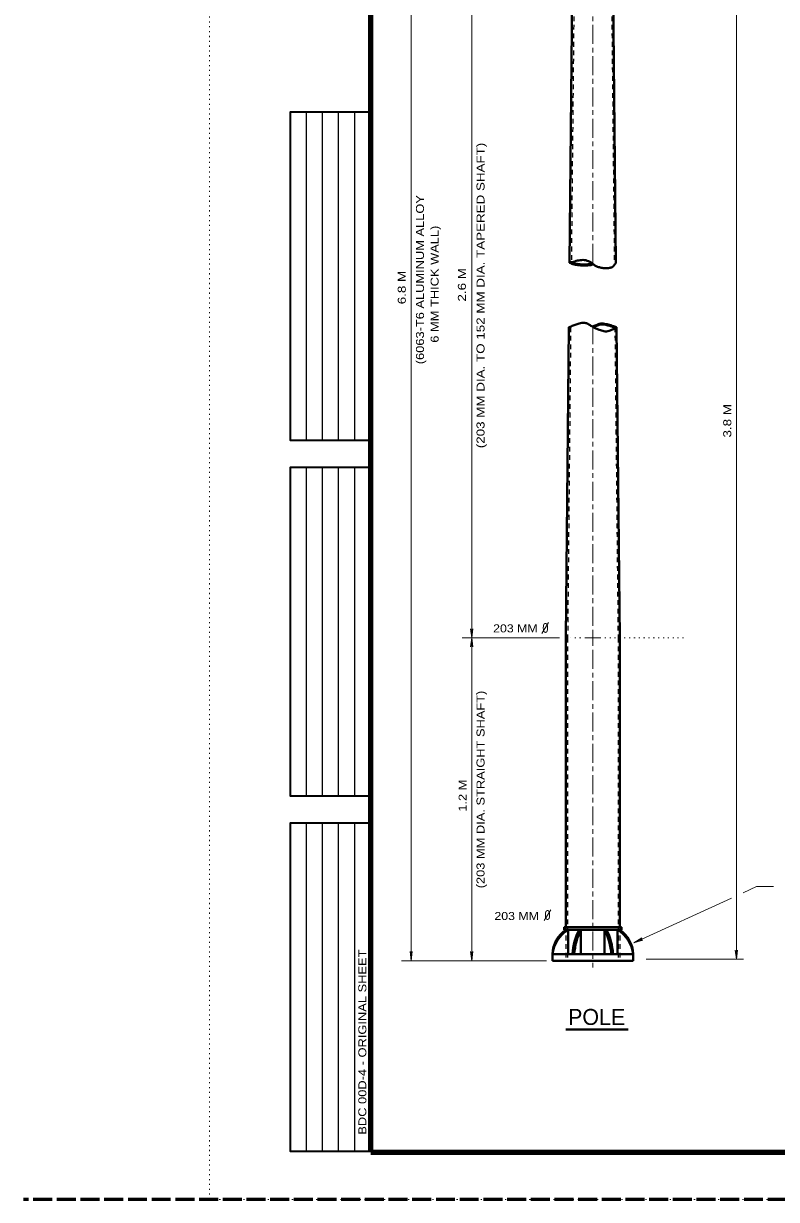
# Model space of a CAD drawing. Extents: x 312583 to 312854, y 144419 to 144597.
# Drawn here: x 312583.5 to 312655, y 144418.6 to 144530.3 of the extents above; entities that cross this region are included whole.
import ezdxf
from ezdxf.enums import TextEntityAlignment as Align

# ---------------------------------------------------------------- set-up
doc = ezdxf.new("R2010")
doc.units = 0
doc.header["$LTSCALE"] = 0.3
for name, pattern in [('DOTTED', [1.5, 0.3, -1.2]), ('LONG_DASH_SHORT_DASH', [9.9, 6, -1.2, 1.5, -1.2]), ('LONG_DASHED', [7.5, 6, -1.5]), ('SHORT_DASHED', [2.7, 1.5, -1.2])]:
    doc.linetypes.add(name, pattern=pattern)
for name, color, linetype, lineweight in [('1', 7, 'Continuous', 35), ('2', 7, 'Continuous', 13), ('62', 7, 'DOTTED', 13), ('63', 7, 'LONG_DASHED', 60)]:
    doc.layers.add(name, color=color, linetype=linetype, lineweight=lineweight)

msp = doc.modelspace()

# ---------------------------------------------------------------- linework, layer by layer
at = {"layer": '1', "lineweight": 40}
for p, q in [((312635.671, 144535.8063), (312635.3874, 144507.5393)), ((312639.5044, 144535.8063), (312639.788, 144507.5393)), ((312635.326, 144501.4136), (312635.0347, 144471.92)), ((312639.8494, 144501.4136), (312640.1484, 144471.92)), ((312635.0347, 144471.92), (312635.0347, 144444.4503)), ((312640.1484, 144471.92), (312640.1484, 144444.4503)), ((312634.8737, 144444.4503), (312637.5877, 144444.4503)), ((312634.8737, 144444.4503), (312634.8737, 144444.205)), ((312640.3017, 144444.4503), (312637.5877, 144444.4503)), ((312640.3017, 144444.4503), (312640.3017, 144444.205)), ((312634.8737, 144444.205), (312637.5877, 144444.205)), ((312635.2417, 144441.8896), (312635.2417, 144444.205)), ((312636.4684, 144444.205), (312636.4684, 144441.974)), ((312640.3017, 144444.205), (312637.5877, 144444.205)), ((312638.707, 144444.205), (312638.707, 144441.974)), ((312639.9414, 144441.8896), (312639.9414, 144444.205)), ((312633.7544, 144441.8896), (312637.5877, 144441.8896)), ((312633.7544, 144441.8896), (312633.7544, 144441.2533)), ((312633.7544, 144441.2533), (312637.5877, 144441.2533)), ((312641.421, 144441.8896), (312637.5877, 144441.8896)), ((312641.421, 144441.2533), (312637.5877, 144441.2533)), ((312641.421, 144441.8896), (312641.421, 144441.2533))]:
    msp.add_line(p, q, dxfattribs=at)
at = {"layer": '1', "linetype": 'SHORT_DASHED', "lineweight": 25}
for p, q in [((312635.832, 144535.8063), (312635.5484, 144507.5393)), ((312639.3434, 144535.8063), (312639.6347, 144507.3553)), ((312635.487, 144501.4136), (312635.1957, 144471.92)), ((312639.6884, 144501.4136), (312639.9874, 144471.92)), ((312635.1957, 144471.92), (312635.1957, 144444.4426)), ((312639.9874, 144471.92), (312639.9874, 144444.4426)), ((312635.0347, 144444.4503), (312635.0347, 144441.2533)), ((312635.1957, 144444.4503), (312635.1957, 144441.2533)), ((312639.9874, 144444.4503), (312639.9874, 144441.2533)), ((312640.1484, 144444.4503), (312640.1484, 144441.2533))]:
    msp.add_line(p, q, dxfattribs=at)
at = {"layer": '1', "linetype": 'LONG_DASH_SHORT_DASH', "lineweight": 13}
for p, q in [((312637.5877, 144507.5393), (312637.5877, 144534.6563)), ((312637.5877, 144473.07), (312637.5877, 144501.4136)), ((312637.5877, 144470.77), (312637.5877, 144440.6016))]:
    msp.add_line(p, q, dxfattribs=at)
at = {"layer": '1', "lineweight": 25}
for p, q in [((312610.4087, 144490.6573), (312610.4087, 144521.8756)), ((312611.9315, 144490.6573), (312611.9315, 144521.8756)), ((312613.4543, 144490.6573), (312613.4543, 144521.8756)), ((312614.9772, 144490.6573), (312614.9772, 144521.8756)), ((312610.4087, 144456.901), (312610.4087, 144488.1192)), ((312611.9315, 144456.901), (312611.9315, 144488.1192)), ((312613.4543, 144456.901), (312613.4543, 144488.1192)), ((312614.9772, 144456.901), (312614.9772, 144488.1192)), ((312610.4087, 144423.1446), (312610.4087, 144454.3629)), ((312611.9315, 144423.1446), (312611.9315, 144454.3629)), ((312613.4543, 144423.1446), (312613.4543, 144454.3629)), ((312614.9772, 144423.1446), (312614.9772, 144454.3629)), ((312634.8737, 144444.4503), (312635.0347, 144444.6036)), ((312640.3017, 144444.4503), (312640.1484, 144444.6036))]:
    msp.add_line(p, q, dxfattribs=at)
at = {"layer": '1', "lineweight": 13}
for q in [(312636.821, 144471.92), (312638.3544, 144471.92)]:
    msp.add_line((312637.5877, 144471.92), q, dxfattribs=at)
at = {"layer": '1', "linetype": 'DOTTED', "lineweight": 13}
msp.add_line((312638.7377, 144471.92), (312646.4044, 144471.92), dxfattribs=at)
at = {"layer": '1', "lineweight": 158}
msp.add_line((312616.5, 144423.0846), (312849, 144423.0846), dxfattribs=at)
msp.add_lwpolyline([(312616.5, 144423.1446), (312616.5, 144585.0846), (312849, 144585.0846)], dxfattribs=at)
at = {"layer": '1'}
for points in [[(312616.5, 144490.6573), (312608.8858, 144490.6573), (312608.8858, 144521.8756), (312616.5, 144521.8756)], [(312616.5, 144456.901), (312608.8858, 144456.901), (312608.8858, 144488.1192), (312616.5, 144488.1192)], [(312616.5, 144423.1446), (312608.8858, 144423.1446), (312608.8858, 144454.3629), (312616.5, 144454.3629)]]:
    msp.add_lwpolyline(points, dxfattribs=at)
at = {"layer": '1', "lineweight": 40}
for centre, radius, start, end in [((312636.6851, 144441.7828), 2.9315, 124.21849, 177.88724), ((312636.9711, 144441.4648), 3.2435, 122.28719, 172.4519), ((312641.5891, 144441.5489), 5.927, 153.35491, 176.59885), ((312641.5891, 144441.5489), 5.7673, 152.55593, 176.59975), ((312633.5888, 144441.5489), 5.7673, 3.40025, 27.44407), ((312633.5888, 144441.5489), 5.927, 3.40115, 26.64509), ((312638.2069, 144441.4648), 3.2435, 7.5481, 57.71281), ((312638.4928, 144441.7828), 2.9315, 2.11276, 55.78151), ((312636.5508, 144441.9708), 0.0799, 180, 270), ((312638.6272, 144441.9708), 0.0799, 270, 0)]:
    msp.add_arc(centre, radius, start, end, dxfattribs=at)
for points in [[(312635.3874, 144507.5393), (312635.878, 144507.6696), (312636.1234, 144507.7616), (312636.3994, 144507.777), (312636.6524, 144507.8076), (312636.936, 144507.777), (312637.1814, 144507.7003), (312637.442, 144507.5623), (312637.5954, 144507.432), (312637.8407, 144507.2556), (312638.1244, 144507.1406), (312638.4847, 144507.0486), (312638.822, 144507.0256), (312639.167, 144507.0486), (312639.4277, 144507.1406), (312639.581, 144507.2786), (312639.788, 144507.5393)], [(312635.3874, 144507.5393), (312635.809, 144507.386), (312636.085, 144507.3323), (312636.4454, 144507.294), (312636.8747, 144507.271), (312637.2734, 144507.317), (312637.5494, 144507.3706), (312637.6184, 144507.4243)], [(312635.4334, 144507.6313), (312635.8397, 144507.478), (312636.1004, 144507.432), (312636.4607, 144507.3936), (312636.8747, 144507.3706), (312637.258, 144507.409), (312637.511, 144507.4626), (312637.5494, 144507.4933)], [(312635.326, 144501.4136), (312635.74, 144501.59), (312635.9087, 144501.659), (312636.2997, 144501.7663), (312636.5374, 144501.8353), (312636.7674, 144501.8506), (312637.051, 144501.7663), (312637.3424, 144501.613), (312637.6414, 144501.4366), (312637.879, 144501.3063), (312638.201, 144501.1683), (312638.6457, 144501.0456), (312638.8757, 144501.0303), (312639.1594, 144501.0916), (312639.4507, 144501.2066), (312639.673, 144501.291), (312639.8494, 144501.4136)], [(312639.8494, 144501.4136), (312639.443, 144501.5593), (312639.305, 144501.613), (312639.052, 144501.682), (312638.8374, 144501.7203), (312638.5844, 144501.7663), (312638.2624, 144501.7586), (312638.1014, 144501.6973), (312637.9174, 144501.6283), (312637.7257, 144501.544), (312637.5724, 144501.4826)], [(312639.8264, 144501.337), (312639.4124, 144501.4826), (312639.282, 144501.5363), (312639.029, 144501.5976), (312638.822, 144501.6436), (312638.5767, 144501.682), (312638.2777, 144501.6743), (312638.1244, 144501.6206), (312637.948, 144501.5516), (312637.7564, 144501.4673), (312637.603, 144501.406)]]:
    msp.add_spline(points, degree=3, dxfattribs=at)
at = {"layer": '2'}
for p, q in [((312620.3377, 144441.2533), (312620.3377, 144566.473)), ((312651.2267, 144441.3913), (312651.2267, 144535.8216)), ((312626.0877, 144471.92), (312626.0877, 144535.7756)), ((312632.7615, 144472.3493), (312633.3978, 144473.369)), ((312625.9804, 144472.7863), (312626.0877, 144472.5103)), ((312626.0877, 144471.92), (312625.9804, 144472.7863)), ((312626.195, 144472.7863), (312626.0877, 144472.5103)), ((312626.0877, 144471.92), (312626.195, 144472.7863)), ((312637.5877, 144471.92), (312637.5877, 144472.6866)), ((312634.4367, 144471.92), (312625.1677, 144471.92)), ((312626.0877, 144471.92), (312625.9804, 144471.0536)), ((312625.9804, 144471.0536), (312626.0877, 144471.3296)), ((312626.0877, 144441.2533), (312626.0877, 144471.92)), ((312626.0877, 144471.92), (312626.195, 144471.0536)), ((312626.195, 144471.0536), (312626.0877, 144471.3296)), ((312637.5877, 144471.92), (312637.5877, 144471.1533)), ((312651.8784, 144447.7163), (312653.1457, 144448.297)), ((312654.737, 144448.297), (312653.1457, 144448.297)), ((312641.4977, 144442.963), (312650.7514, 144447.2026)), ((312632.9595, 144445.0866), (312633.5958, 144446.1063)), ((312641.4977, 144442.963), (312642.2414, 144443.423)), ((312641.4977, 144442.963), (312642.3257, 144443.2236)), ((312642.2414, 144443.423), (312642.0344, 144443.2083)), ((312642.3257, 144443.2236), (312642.0344, 144443.2083)), ((312620.2304, 144442.1196), (312620.3377, 144441.8436)), ((312620.3377, 144441.2533), (312620.2304, 144442.1196)), ((312620.445, 144442.1196), (312620.3377, 144441.8436)), ((312620.3377, 144441.2533), (312620.445, 144442.1196)), ((312625.9804, 144442.1196), (312626.0877, 144441.8436)), ((312626.0877, 144441.2533), (312625.9804, 144442.1196)), ((312626.195, 144442.1196), (312626.0877, 144441.8436)), ((312626.0877, 144441.2533), (312626.195, 144442.1196)), ((312651.1194, 144442.2576), (312651.2267, 144441.9816)), ((312651.2267, 144441.3913), (312651.1194, 144442.2576)), ((312651.334, 144442.2576), (312651.2267, 144441.9816)), ((312651.2267, 144441.3913), (312651.334, 144442.2576)), ((312633.1794, 144441.2533), (312619.4177, 144441.2533)), ((312651.9167, 144441.3913), (312642.6477, 144441.3913))]:
    msp.add_line(p, q, dxfattribs=at)
at = {"layer": '2', "linetype": 'DOTTED'}
msp.add_line((312636.4377, 144471.92), (312635.4947, 144471.92), dxfattribs=at)
at = {"layer": '2', "lineweight": 40}
msp.add_line((312635.0255, 144434.7262), (312640.943, 144434.7262), dxfattribs=at)
at = {"layer": '62'}
msp.add_line((312601.2, 144418.5846), (312601.2, 144596.7846), dxfattribs=at)
msp.add_lwpolyline([(312601.2, 144418.5846), (312853.5, 144418.5846), (312853.5, 144596.7846)], dxfattribs=at)
at = {"layer": '63'}
msp.add_line((312851.75, 144418.5846), (312583.526, 144418.5846), dxfattribs=at)

# ---------------------------------------------------------------- texts
at = {"layer": '1', "width": 1.2}
msp.add_text('BDC 00D-4 - ORIGINAL SHEET', height=0.7614, rotation=90, dxfattribs=at).set_placement((312616.0832, 144424.7374))
at = {"layer": '2'}
for s, width, p in [('(203 MM DIA. TO 152 MM DIA. TAPERED SHAFT)', 1.25, (312627.3077, 144489.9325)), ('(6063-T6 ALUMINUM ALLOY', 1.2, (312621.556, 144497.9075)), ('6 MM THICK WALL)', 1.2, (312622.9474, 144499.954)), ('2.6 M', 1.25, (312625.5373, 144503.8624)), ('6.8 M', 1.25, (312619.8273, 144503.6046)), ('3.8 M', 1.25, (312650.7375, 144490.9483)), ('(203 MM DIA. STRAIGHT SHAFT)', 1.2, (312627.3077, 144448.1363)), ('1.2 M', 1.2, (312625.6081, 144455.4107))]:
    msp.add_text(s, height=0.76, rotation=90, dxfattribs=dict(at, width=width)).set_placement(p)
at = {"layer": '2', "width": 0.85}
for p in [(312633.0911, 144472.403), (312633.2892, 144445.1403)]:
    msp.add_text('0', height=0.92, dxfattribs=at).set_placement(p, align=Align.CENTER)
at = {"layer": '2', "width": 1.15}
for p in [(312628.1266, 144472.4423), (312628.2465, 144445.1264)]:
    msp.add_text('203 MM', height=0.76, dxfattribs=at).set_placement(p)
at = {"layer": '2'}
msp.add_text('POLE', height=1.52, dxfattribs=at).set_placement((312637.9546, 144435.1604), align=Align.CENTER)

doc.saveas('drawing.dxf')
